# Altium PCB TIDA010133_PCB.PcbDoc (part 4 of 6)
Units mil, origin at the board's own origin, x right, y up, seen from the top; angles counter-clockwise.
Board outline 4100 x 6400 mil, 8 copper layers (Top Layer, Ground 1, Signal 1, Power 1, Ground 2, Signal 2, Power 2, Bottom Layer), stack 60.4 mil thick; 587 components, 322 nets, 1661 pads, 859 vias.
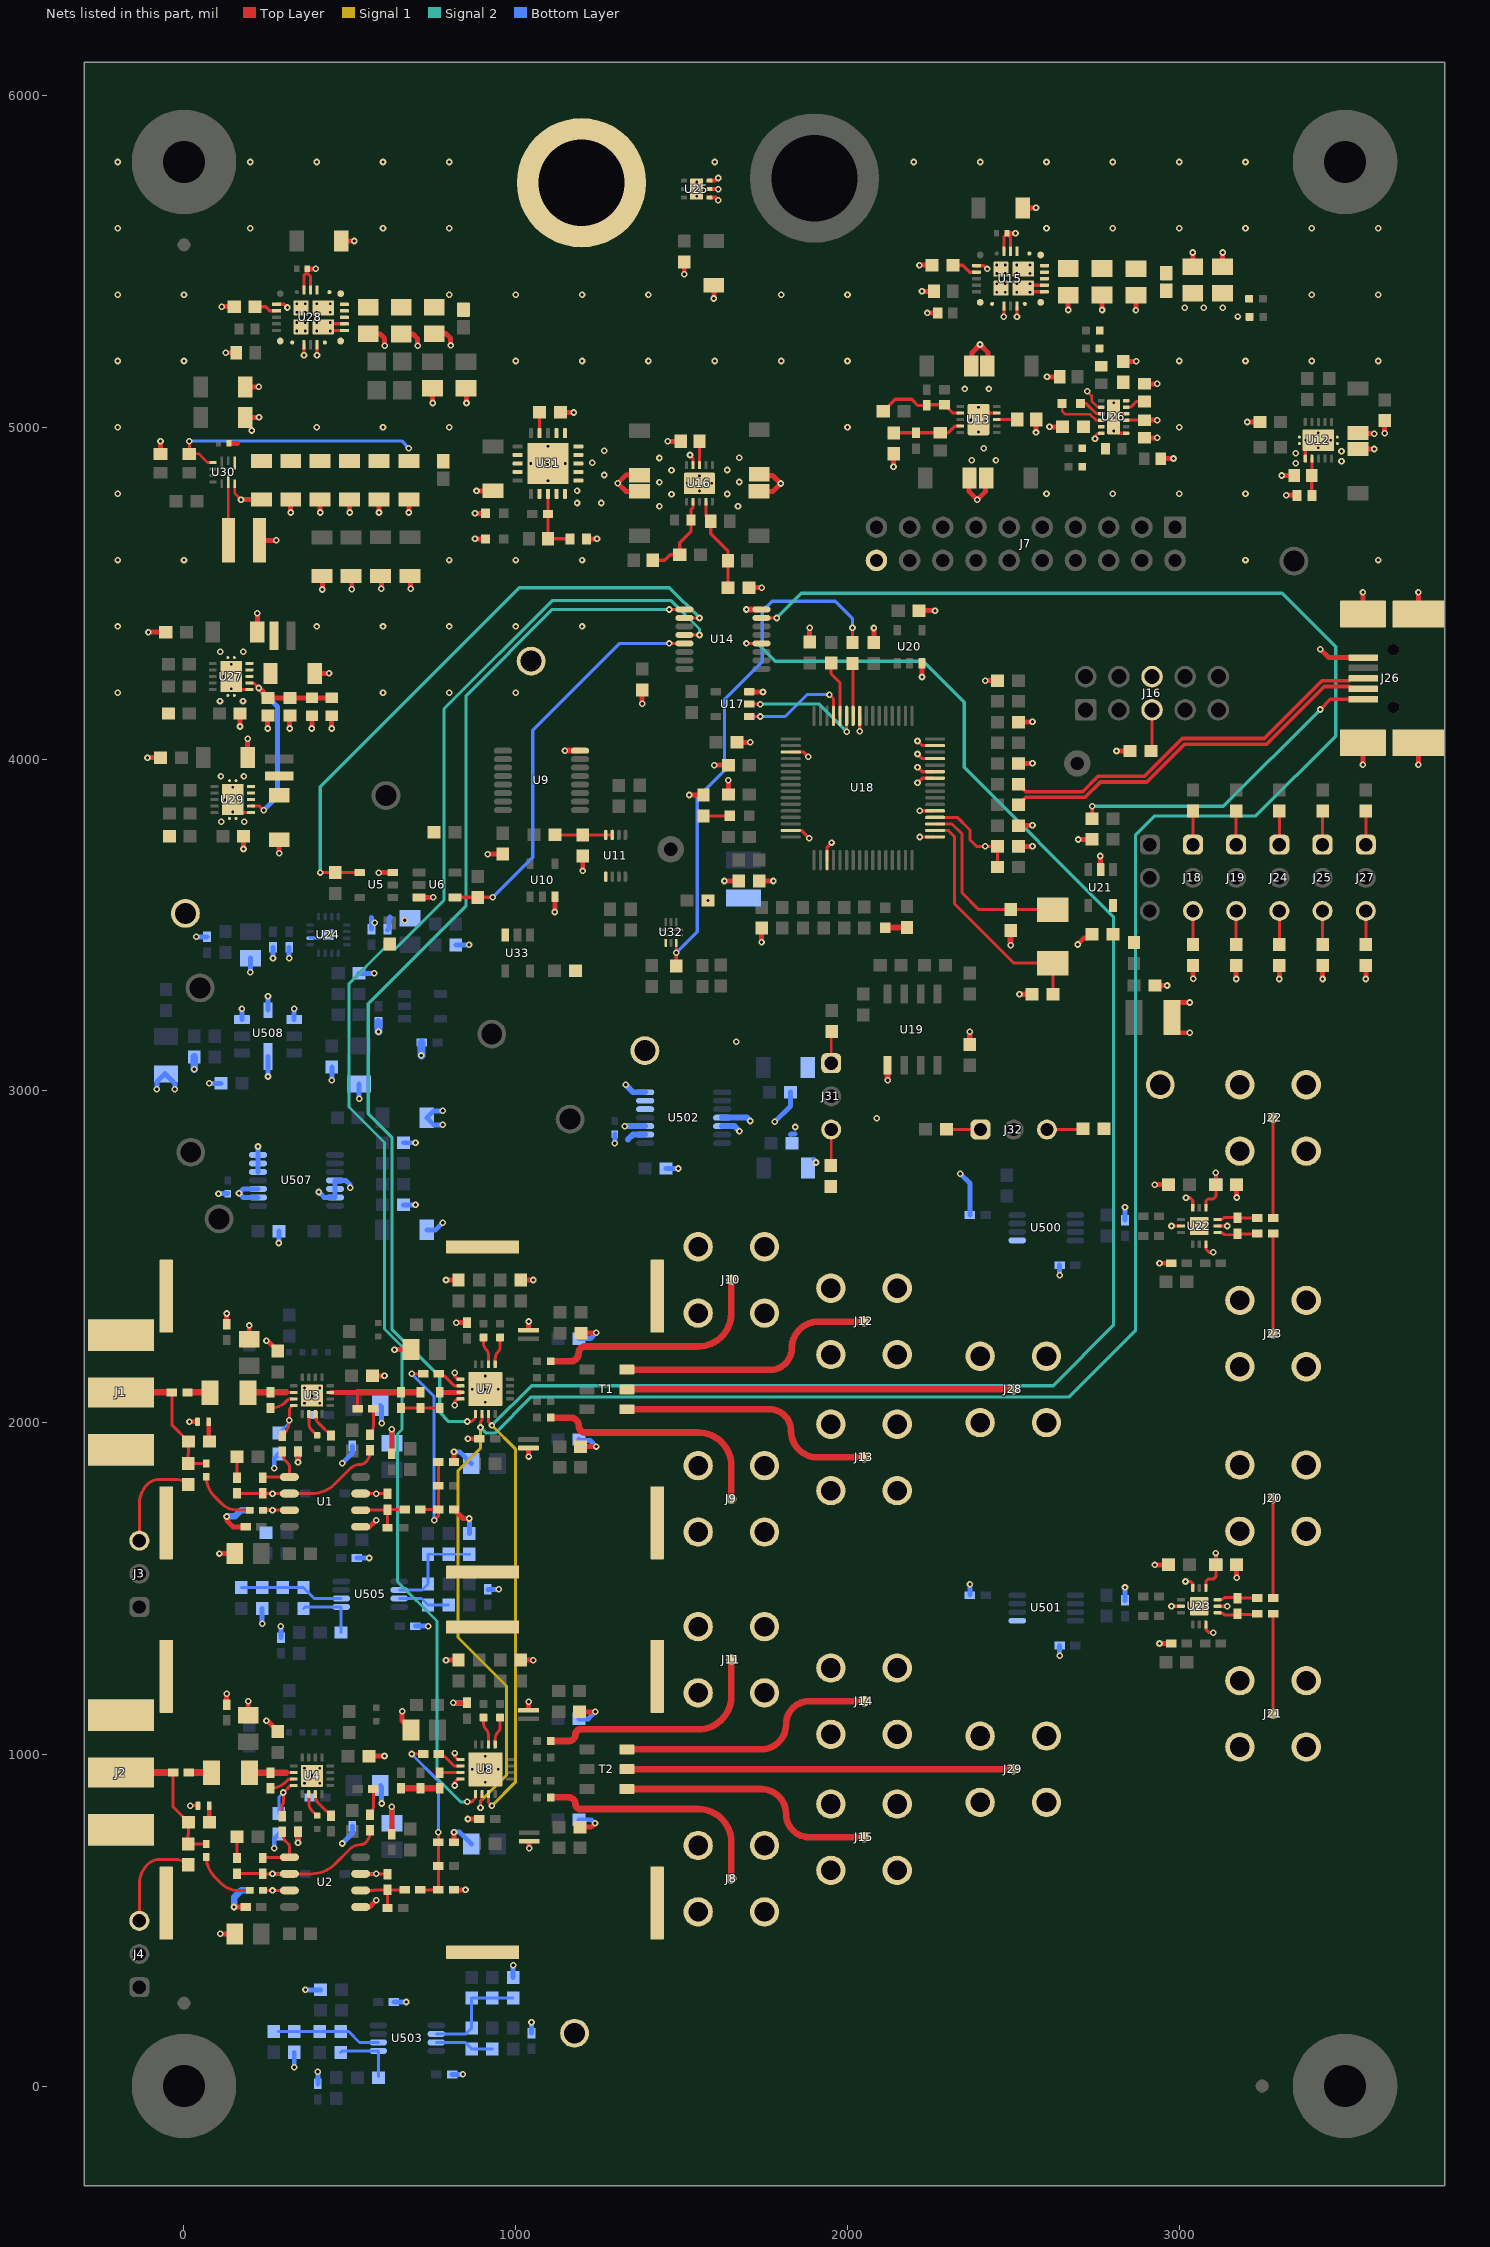
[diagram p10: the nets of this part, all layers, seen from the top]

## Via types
v1: diameter 20, hole 10, Top Layer to Bottom Layer, tented top, 776 vias
v2: diameter 19.68, hole 7.87, Top Layer to Bottom Layer, tented bottom, 82 vias
v3: diameter 19.68, hole 7.87, Top Layer to Bottom Layer, 1 vias

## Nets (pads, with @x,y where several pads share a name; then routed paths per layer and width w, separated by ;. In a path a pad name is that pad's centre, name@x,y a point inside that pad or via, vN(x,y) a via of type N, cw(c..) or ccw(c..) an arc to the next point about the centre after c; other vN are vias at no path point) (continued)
GND: C1.2 C2.2 C3.1 C4.1 C7.2 C8.2 C9.1 C10.1 C13.1 C14.2 C15.2 C16.2 C17.2 C19.2 C20.2 C21.2 C22.1 C23.2 C24.2 C26.2 C27.1 C28.1 C29.2 C30.2 C33.2 C34.2 C35.2 C36.2 C37.2 C39.2 C40.2 C41.2 C42.2 C43.2 C44.2 C45.2 C46.2 C47.2 C48.2 C49.2 C50.2 C51.2 C52.1 C53.1 C54.2 C55.2 C56.2 C57.2 C58.2 C61.2 C64.1 C65.1 C66.1 C68.2 C70.2 C71.2 C76.1 C78.2 C79.2 C80.1 C81.1 C82.1 C83.1 C84.1 C85.1 C86.1 C87.1 C88.1 C89.1 C90.2 C91.2 C92.2 C93.2 C94.2 C95.1 C96.1 C97.1 C98.2 C99.2 C104.1 C105.2 C106.2 C107.2 C108.2 C109.2 C110.2 C111.2 C112.2 C113.1 C114.1 C115.2 C116.2 C117.1 C118.1 C119.1 C121.2 C122.1 C123.2 C124.2 C125.1 C126.1 C127.1 C128.1 C130.2 C131.1 C132.1 C133.1 C134.2 C135.1 C136.2 C137.2 C138.2 C139.2 C140.2 C141.2 C142.2 C143.2 C144.2 C145.2 C146.2 C147.2 C500.2 C501.2 C502.2 C503.2 C504.2 C505.2 C506.2 C507.2 C510.1 C511.1 C512.2 C513.2 C514.2 C523.2 C524.2 C525.2 C526.2 C528.2 C529.2 C530.2 C531.2 C532.2 C534.1 C535.1 C536.2 C537.2 C538.2 C539.2 C540.1 C541.1 C542.2 C543.2 C544.2 C545.2 C546.2 C547.2 C548.2 C549.2 C550.2 C551.1 C552.1 C554.2 C555.2 C556.2 C557.2 C559.2 C560.2 C561.2 C562.2 C563.2 C564.2 C565.2 C566.2 C567.2 C568.2 C569.2 H3.1 H4.1 H5.1 H6.1 H7.1 H8.1 H9.1 H10.1 H11.1 H12.1 H13.1 H14.1 J1.2 J1.3 J1.4 J1.5 J2.2 J2.3 J2.4 J2.5 J7.20 J8.2 J8.3 J8.4 J8.5 J9.2 J9.3 J9.4 J9.5 J10.2 J10.3 J10.4 J10.5 J11.2 J11.3 J11.4 J11.5 J12.2 J12.3 J12.4 J12.5 J13.2 J13.3 J13.4 J13.5 J14.2 J14.3 J14.4 J14.5 J15.2 J15.3 J15.4 J15.5 J16.6 J20.2 J20.3 J20.4 J20.5 J21.2 J21.3 J21.4 J21.5 J22.2 J22.3 J22.4 J22.5 J23.2 J23.3 J23.4 J23.5 J26.5 J26.6 J26.7 J26.8 J26.9 J28.2 J28.3 J28.4 J28.5 J29.2 J29.3 J29.4 J29.5 J30.1 L1.1 L2.1 L16.2 R42.1 R44.1 R48.1 R49.1 R60.1 R61.1 R63.1 R64.1 R70.1 R76.1 R77.1 R82.1 R85.1 R91.1 R98.2 R105.1 R106.1 R110.1 R112.1 R116.1 R117.1 R139.2 R142.1 R149.1 R150.1 R151.1 R157.1 R161.1 R163.1 R166.1 R171.1 R172.1 R175.1 R176.1 R179.1 R503.1 R505.1 R508.2 R511.1 R513.1 R514.1 R515.1 R516.1 R517.1 R522.1 R542.1 R548.2 R550.1 R551.1 R552.1 R553.1 R555.1 TP1.1 TP8.1 TP9.1 TP11.1 TP13.1 U1.5 U2.5 U3.17 U4.17 U5.3 U6.3 U7.5 U7.8 U7.17 U8.5 U8.8 U8.17 U9.8 U10.3 U11.1 U12.6 U12.11 U13.4 U13.11 U14.8 U15.1 U15.2 U15.3 U15.5 U15.6 U15.7 U15.8 U15.9 U15.16 U15.17 U15.20 U15.25 U15.26 U15.28 U16.4 U16.11 U17.3 U18.1 U18.5 U18.10 U18.11 U18.13 U18.15 U18.25 U18.35 U18.47 U18.51 U19.5 U20.3 U21.2 U22.3 U22.5 U22.9 U22.11 U22.13 U23.3 U23.5 U23.9 U23.11 U23.13 U24.6 U24.17 U25.1 U25.2 U25.3 U25.7@1545.46,5718.18 U26.1 U26.4 U26.13 U27.6 U27.11 U28.1 U28.2 U28.3 U28.5 U28.6 U28.7 U28.8 U28.9 U28.16 U28.17 U28.20 U28.25 U28.26 U28.28 U29.6 U29.11 U30.3 U31.2 U31.4 U31.5 U31.6 U31.7 U31.8 U31.9 U31.10 U31.11 U31.12 U31.17 U31.18 U31.19 U31.21 U32.3 U33.3 U500.5 U501.5 U502.2 U502.3 U502.5 U502.6 U502.7 U502.11 U502.12 U507.2 U507.3 U507.5 U507.6 U507.7 U507.11 U507.12 U507.13 U508.3 U508.4 U508.5 U508.8 | length 13695.3
  Top Layer w7.87: U30.3@153.04,4830.24 153.04,4801.23 v1(171.99,4782.28)
  Top Layer w9: v1(19,845) L2.1@42.27,845 ; v1@2211.49,4054.74 2225.36,4040.87 U18.15@2264.25,4040.87
  Top Layer w9.45: U27.11@143.97,4209.63 U27.6@197.12,4209.63 ; v2(147,3840.6) 148.97,3838.63 U29.6@202.12,3838.63 ; v1(1525.46,4916.66) 1534.32,4907.8 U16.4@1534.32,4886.12 ; v2(2417.74,5023.48) 2417.74,5038.05 2422.86,5043.17 U13.4@2450.22,5043.17 ; v2(2802.59,4989.06) 2812.43,4989.06 2819.13,4982.37 U26.1@2839.8,4982.37 ; v2(2802.59,5031.38) 2812.43,5041.22 U26.4@2839.99,5041.22 ; v1(2976.73,1446.17) U23.5@3005.54,1446.17 ; v1(2976.73,2592.43) U22.5@3005.54,2592.43 ; v1(3018.95,1520.77) 3034.4,1520.77 3040.98,1514.2 U23.3@3040.98,1501.29 ; v1(3020.48,2677.9) 3032.29,2677.9 3040.98,2669.21 U22.3@3040.98,2647.55 ; U23.9@3080.35,1391.05 3080.35,1377.04 3090.68,1366.71 v1(3102.68,1366.71) ; U22.9@3080.35,2537.31 3080.35,2523.29 3090.68,2512.96 v1(3102.68,2512.96) ; U23.11@3115.78,1446.17 v1(3144.59,1446.17) ; U22.11@3115.78,2592.43 v1(3144.59,2592.43)
  Top Layer w9.84: U28.20@278.94,5371.12 301.88,5371.12 v1(311.8,5361.2) ; v1(361.61,5217.29) U28.3@361.61,5249.07 ; U28.17@361.61,5414.43 361.61,5457.43 370.71,5466.53 ; C104.1@370.71,5477.25 370.71,5466.53 ; U28.16@381.3,5414.43 381.3,5455.94 370.71,5466.53 ; v1(400.98,5217.29) U28.5@400.98,5249.07 ; v2(440.35,5290.41) 442.32,5292.38 U28.8@483.66,5292.38 ; v2(440.35,5316) 444.29,5312.06 U28.9@483.66,5312.06 ; v1(816.12,905.78) 816.12,915.79 825.48,925.16 U8.8@833.57,925.16 ; v1(816.12,1003.59) 816.12,993.58 825.48,984.21 U8.5@833.57,984.21 ; v1(816.12,2052.03) 816.12,2062.04 825.48,2071.41 U7.8@833.57,2071.41 ; v1(816.12,2149.85) 816.12,2139.84 825.48,2130.47 U7.5@833.57,2130.47 ; U18.47@1829.21,3784.97 1860.93,3784.97 v1(1884.94,3760.96) ; U18.35@1829.21,4021.19 1868.45,4021.19 v1(1882.15,4007.49) ; U18.51@1938.46,3695.4 1938.46,3734.64 v1(1952.16,3748.34) ; v1@2036.89,4082.93 v1(2036.89,4084.18) U18.25@2036.89,4130.44 ; v1(2211.31,3928.75) 2225.01,3942.45 U18.10@2264.25,3942.45 ; v1(2211.31,3975.83) 2225.01,3962.13 U18.11@2264.25,3962.13 ; v1(2211.31,4015.2) 2225.01,4001.5 U18.13@2264.25,4001.5 ; v1@2216.32,3765.28 U18.1@2264.25,3765.28 ; v1@2216.32,3844.02 U18.5@2264.25,3844.02 ; U15.20@2388.98,5487.62 2411.92,5487.62 v1(2421.84,5477.7) ; v1(2471.65,5333.8) U15.3@2471.65,5365.57 ; U15.17@2471.65,5530.93 2471.65,5573.94 C13.1@2480.75,5583.03 ; C13.1@2480.75,5585 C13.1@2480.75,5583.03 ; U15.16@2491.34,5530.93 2491.34,5572.44 C13.1@2480.75,5583.03 ; v1(2511.02,5333.8) U15.5@2511.02,5365.57 ; v2(2550.39,5406.91) 2552.36,5408.88 U15.8@2593.7,5408.88 ; v2(2550.39,5432.5) 2554.33,5428.57 U15.9@2593.7,5428.57 ; U12.6@3380.26,4905.85 3380.26,4959 v2(3382.23,4960.96)
  Top Layer w11.81: U25.1@1583.84,5692.59 1602.91,5692.59 v1(1610.82,5684.67) ; U25.2@1583.84,5718.18 v1(1610.7,5718.18) ; U25.3@1583.84,5743.77 1602.91,5743.77 v1(1610.82,5751.68)
  Top Layer w13.78: v1(16.37,2002.3) L1.1@40.62,2002.29
  Top Layer w15: v1@-109.88,4004.34 R172.1@-70.99,4004.34 ; v1(-107.23,4382.46) R106.1@-55.53,4382.46 ; R175.1@-70.89,4920 v1(-70.89,4958.39) ; v1(106.8,1604.98) C4.1@152.81,1604.98 ; v1(108.81,458.73) C3.1@152.81,458.73 ; v1(113.82,5364) C147.2@151.5,5364 ; v1(125.63,5225) R171.1@157.41,5225 ; C2.2@128.74,1149.83 v1(128.74,1182.57) ; C1.2@128.74,2296.08 v1(128.74,2328.83) ; v1(128.9,1716.99) 128.9,1704.7 147.8,1685.8 C10.1@185.56,1685.8 ; C113.1@135.5,4952 161.37,4952 ; v1(150.81,539.55) C9.1@185.56,539.55 ; v1@168.66,4098.53 R112.1@168.66,4137.42 ; v1(171.99,4782.28) C117.1@233.46,4782.28 ; v1@179.25,3729.11 R176.1@179.25,3768 ; C116.2@186.1,5122.02 v1(225.76,5122.02) ; C115.2@186.52,5030.35 v1(226.17,5030.35) ; C136.2@191.82,4004.42 v1(191.82,4061.75) ; C8.2@193.69,1117.59 v1(193.69,1159.59) ; C7.2@196.69,2250.84 v1(196.69,2292.84) ; C124.2@221.3,4383.56 v1(221.3,4439.44) ; L16.2@227.67,4659.45 v1(278.06,4659.45) ; v1(248.46,1100.66) 251.58,1100.66 C16.2@283.22,1069.01 ; v1(248.46,2246.91) 251.58,2246.91 C15.2@283.22,2215.27 ; v1@252.25,4092.28 C132.1@252.25,4131.17 ; v1@287,3716.28 C134.2@287,3755.17 ; v1@318.44,4092.28 C133.1@318.44,4131.17 ; v1(321.7,4743.23) C118.1@321.7,4782.28 ; v1(343.72,733.66) C20.2@343.72,766.41 ; v1(343.72,1879.92) C19.2@343.72,1912.66 ; C104.1@371.46,5478 v1(397.33,5478) ; v1@385.25,4092.28 R116.1@385.25,4131.17 ; C123.2@398.36,4258.53 v1@437.25,4258.53 ; v1(410.39,4743.23) C125.1@410.39,4782.28 ; v1(417.04,4511.36) C140.2@417.04,4550.97 ; v1@445.25,4092.28 R117.1@445.25,4131.17 ; C109.2@473.82,5562 v1(513.47,5562) ; v1(499.4,4743.23) C126.1@499.4,4782.28 ; v1(505.72,4512) C139.2@505.72,4551.04 ; U2.5@532.36,539.55 559.91,539.55 v1(579.91,559.55) ; U1.5@532.36,1685.81 559.91,1685.81 v1(579.91,1705.81) ; C110.2@555.41,5281.85 590.8,5281.85 604.77,5267.88 v1(604.77,5246.47) ; C23.2@557.85,994.64 v1(604.54,994.64) ; C24.2@567.85,2140.9 v1(604.54,2140.9) ; v1@587.72,3657.93 U5.3@629.7,3657.93 ; v1(587.85,4743.23) C127.1@587.85,4782.28 ; v1@594.76,4513.76 C138.2@594.76,4553.17 ; C27.1@626.44,1905.32 v1(626.44,1980.08) ; C28.1@626.6,759.22 v1@626.6,841.85 ; v1(634.68,2219.82) C29.2@684.23,2219.82 ; C111.2@654.83,5281.57 690.21,5281.57 704.18,5267.6 v1(704.18,5246.19) ; v1(657.51,1129.58) 657.51,1100.29 C30.2@684.23,1073.57 ; v1(677.7,4743.23) C128.1@677.7,4782.28 ; v1(683.44,4513.76) C137.2@683.44,4553.81 ; U6.3@708.84,3583.13 v1@750.82,3583.13 ; v1(749.55,5073.34) C145.2@749.55,5118.31 ; C112.2@754.37,5282.42 789.76,5282.42 803.72,5268.45 v1(803.72,5247.04) ; v1(789.89,1283.56) R49.1@827.59,1283.56 ; v1(789.89,2429.81) R48.1@827.59,2429.81 ; v1(812.12,1154.88) C37.2@853.42,1154.88 ; C34.2@813.97,591.49 v1(848.72,591.49) ; R44.1@813.97,734.61 v1(813.97,765.33) ; C33.2@813.97,1737.75 840.99,1710.72 v1(860.28,1710.72) ; R42.1@813.97,1880.86 v1(813.97,1911.59) ; v1(820.48,2301.02) C36.2@853.53,2301.02 ; v1(851.59,5073.38) C146.2@851.59,5118.35 ; v1(855.91,804.88) C40.2@890.66,804.88 ; v1(855.91,1951.14) C39.2@890.66,1951.14 ; v1(877.1,4664) C131.1@908.88,4664 ; v1(877.1,4741) C135.1@908.88,4741 ; v1(881.9,4808.44) C130.2@932,4808.44 ; v1(915.99,3713.45) C41.2@961.5,3713.45 ; R61.1@1015.31,1283.56 v1(1053.01,1283.56) ; R60.1@1015.31,2429.81 v1(1053.01,2429.81) ; C46.2@1038.87,1135.55 v1(1038.87,1158.24) ; v1(1038.87,1897.39) C45.2@1038.87,1920.08 ; C44.2@1038.87,2281.8 v1(1038.87,2304.49) ; v1(1040.74,716.47) C47.2@1040.74,737.33 ; v1(1118.13,3539.26) U10.3@1118.13,3584.77 ; C141.2@1134.72,5045 v1(1174.72,5045) ; C50.2@1192.96,1128.13 v1(1240.08,1128.13) ; C51.2@1193.63,780.31 1227.67,780.32 v1(1239.23,791.87) ; C49.2@1195.79,1927.55 v1(1242.73,1927.55) ; C48.2@1196.53,2270.11 v1@1242.34,2270.11 ; v1(1202.08,3662.95) C52.1@1202.08,3708.45 ; R179.1@1213.21,4664 v1(1244.99,4664) ; C78.2@1373,4856.07 1332.07,4856.07 v1(1307.76,4831.76) 1332.23,4807.3 C79.2@1373.14,4807.3 ; v1@1381.09,4166.97 C55.2@1381.09,4208.95 ; v1(1458.2,4958) C80.1@1496.91,4958 ; v1(1508,5461.32) C57.2@1508,5499.01 ; v1(1523.43,3891.93) R110.1@1566.06,3891.93 ; v1(1597,5388.49) C61.2@1597,5428.14 ; v1(1598.39,3981.82) C65.1@1641.02,3981.82 ; v1(1629.14,3632.41) C70.2@1671.77,3632.41 ; C66.1@1641.02,3893.39 v1(1641.02,3936.02) ; C64.1@1666.61,4050.71 v1(1707.23,4050.71) ; R105.1@1702.99,4517 v1(1741.71,4517) ; U17.3@1704.02,4203.14 1704.46,4202.7 1745.09,4202.7 v1(1745.53,4202.26) ; C71.2@1733.14,4806.2 1774.04,4806.2 v1(1798.51,4830.67) 1774.2,4854.98 C68.2@1733.27,4854.98 ; C76.1@1734.18,3632.41 v1(1776.81,3632.41) ; v1(1741.14,3447.68) C81.1@1741.14,3490.31 ; C82.1@1886.08,4352.56 v1(1886.08,4396.36) ; C83.1@2079.77,4351.38 v1(2079.77,4395.18) ; v1(2139,4881.76) R85.1@2139,4920.47 ; C84.1@2216.16,4447.41 v1(2263.8,4447.41) ; v1(2216.96,5489) C144.2@2254.65,5489 ; v1(2224.83,5410) R82.1@2260.55,5410 ; v1(2224.88,4247.61) U20.3@2224.88,4288.39 ; C26.2@2367.06,4847 2367.06,4806.07 v1(2391.36,4781.76) 2415.83,4806.23 C35.2@2415.83,4847 ; C43.2@2375.44,5184.48 2375.44,5225.41 v1(2399.74,5249.72) 2424.21,5225.25 C42.2@2424.21,5185 ; v1(2415.75,4236.45) C89.1@2452.43,4236.45 ; C13.1@2480.75,5585 v1(2506.62,5585) ; R139.2@2515.43,3799.63 v1@2557.41,3799.63 ; C86.1@2515.43,3737.23 v1@2557.41,3737.23 ; C87.1@2515.43,3986.84 v1@2557.41,3986.84 ; C88.1@2515.43,4111.64 v1@2557.41,4111.64 ; C105.2@2528.76,5661.92 v1(2568.41,5661.92) ; v1(2568.54,4984.77) C53.1@2568.54,5023.48 ; v1(2601.62,5152.29) R98.2@2640.33,5152.29 ; v1(2609.29,5001.85) C121.2@2648.01,5001.85 ; v1(2665.55,5353.93) C106.2@2665.55,5398.9 ; v1(2694.43,3441.24) 2714.35,3461.17 2726.67,3461.17 C93.2@2737.88,3472.37 ; v1@2695.89,3757.97 C92.2@2737.88,3757.97 ; U21.2@2762.9,3665.52 v1@2762.9,3707.5 ; v1(2767.59,5353.98) C107.2@2767.59,5398.95 ; v1(2811.18,4024.35) R142.1@2852.02,4024.35 ; C122.1@2832,5198.99 v1(2870.72,5198.99) ; v1(2869.65,5352.79) C108.2@2869.65,5397.75 ; C119.1@2895,4968.39 v1(2933.72,4968.39) ; C114.1@2895,5131.15 v1(2933.72,5131.15) ; v1(2925.99,1570.84) C97.1@2967.67,1570.84 ; v1(2925.99,2717.1) C96.1@2967.67,2717.1 ; C95.1@2926.85,3317.56 v1(2963.54,3317.56) ; v1(2940.78,1333.94) R150.1@2975.52,1333.94 ; v1(2940.78,2480.19) R149.1@2975.52,2480.19 ; R91.1@2944.21,4906 v1(2982.93,4906) ; v1(3031.67,3175.09) 3001.29,3175.09 2978.03,3198.35 C94.2@2978.03,3220.71 2978.03,3243.07 3001.29,3266.33 v1(3031.67,3266.33) ; C142.2@3041,5483.98 v1(3041,5526.98) ; v1@3041.57,3338.52 R151.1@3041.57,3378.36 ; C143.2@3131,5483.98 v1(3131,5526.98) ; v1(3171.8,3337.13) R157.1@3171.8,3378.36 ; v1(3173.34,1532.14) C99.2@3173.34,1570.84 ; v1(3173.34,2678.4) C98.2@3173.34,2717.1 ; v1(3205.32,5016.08) R76.1@3243.01,5016.08 ; v1(3302.04,3337.13) R161.1@3302.04,3378.36 ; v1(3309.11,4855) C22.1@3346.8,4855 ; v1(3322.72,4795.64) R77.1@3354.03,4795.64 ; v1(3425.74,4331.25) 3450.81,4306.18 J26.5@3554.92,4306.18 ; v1(3432.28,3337.13) R163.1@3432.28,3378.36 ; C14.2@3538.61,4935.02 v1(3588.11,4935.02) ; C21.2@3538.61,4981.18 v1(3588.11,4981.18) ; v1(3553.94,3982.93) J26.7@3553.94,4049.29 ; J26.9@3553.94,4437.09 v1(3553.94,4503.45) ; v1(3562.51,3337.13) R166.1@3562.51,3378.36 ; v1(3619.26,4982.41) R70.1@3619.26,5020.09 ; v1(3721.26,3982.93) J26.6@3721.26,4049.29 ; J26.8@3721.26,4437.09 v1(3721.26,4503.45)
  Top Layer w17.72: v1(1148.34,4025.4) U9.8@1193.85,4025.4 ; v1(1695.46,4451.08) U14.8@1740.97,4451.08 ; v1(2121.09,3032.24) U19.5@2121.09,3077.04 ; C85.1@2368.57,3140.03 v1(2368.57,3177.78) ; v1(2492.03,3438.65) C90.2@2492.03,3482.86 ; v1(2518.67,3291.29) C91.2@2556.42,3291.29
  Bottom Layer w6: 412.32,3460.15 413.49,3461.33 426.85,3461.33 v3(435.51,3470)
  Bottom Layer w9: U24.6@380.39,3460.15 412.32,3460.15
  Bottom Layer w15: v1(-81.81,3004.78) -81.81,3027.35 -57.19,3051.96 -27.48,3022.25 v1(-27.48,3004.78) ; v1(36.71,3464.09) C567.2@69.46,3464.09 ; v1(75.91,3022.59) R553.1@111.61,3022.59 ; v1(103.83,2689.86) R555.1@131.92,2689.86 ; U508.3@174.6,3214.49 v1(174.6,3247.27) ; v1(200.18,3357.84) C566.2@200.18,3399.84 ; U507.2@223.11,2678.73 178.35,2678.73 v1(165.74,2691.35) 178.71,2704.32 U507.3@223.11,2704.32 ; U507.5@223.11,2755.5 U507.6@223.11,2781.09 U507.7@223.11,2806.68 ; U507.7@223.11,2807.95 v1(223.11,2832.28) ; v1(235.75,1393.25) R550.1@235.75,1439.13 ; v1(253.34,3043.13) U508.8@253.34,3103.46 ; U508.4@253.34,3243.23 v1(253.34,3285.23) ; v1(268.49,3399.85) C565.2@268.49,3432.59 ; v1(272.05,716.37) 272.05,745.12 C563.2@286.05,759.12 ; v1(272.05,1862.63) 272.05,1891.37 C562.2@286.05,1905.37 ; v1(286.1,2541.12) R548.2@286.1,2576.82 ; C564.2@291.96,1351.5 v1(291.96,1385.96) ; v1(317.11,3399.85) C561.2@317.11,3432.59 ; U508.5@332.08,3214.49 v1(332.08,3247.27) ; v1(332.33,56.28) R542.1@332.33,101.63 ; v1(343.72,733.66) C560.2@343.72,766.41 ; v1(343.72,1879.92) C559.2@343.72,1912.66 ; v1(366.03,290.04) R505.1@412.08,290.04 ; C557.2@403.4,6.5 v1(403.4,42.88) ; v1(406.46,2694.96) 422.7,2678.73 U507.13@455.4,2678.73 U507.12@455.4,2704.32 U507.11@455.4,2729.91 488.09,2729.91 500.95,2717.06 v1(500.95,2707.55) ; v1(445.55,3032.22) C554.2@445.55,3071.5 ; v1(477.34,731.08) 507.45,761.19 C552.1@507.45,783.25 ; v1(477.34,1877.34) 507.45,1907.45 C551.1@507.45,1929.51 ; C550.2@521.05,1591.52 v1(558.2,1591.52) ; v1(528.03,2975.91) C548.2@528.03,3020.31 ; C549.2@528.03,3354.36 v1(573.78,3354.36) ; C547.2@564.76,3487.4 564.76,3521.81 ; C544.2@592,905.47 596,901.47 v1(596,851.47) ; C545.2@592,2051.73 596,2047.73 v1(596,1997.73) ; C543.2@613.38,3485.43 617.69,3489.74 617.69,3518.36 621.34,3522.01 621.34,3523.36 ; C540.1@626.44,1938.08 v1(626.44,1980.08) ; C541.1@626.75,792.14 v1(626.75,842.01) ; C542.2@632.87,253.22 v1(669.72,253.22) ; C539.2@661.04,2656.29 v1(697.72,2656.29) ; C538.2@661.24,2843.49 v1(697.93,2843.49) ; C537.2@697.62,1386 v1(736.53,1386) ; C535.1@731.9,2581.09 758.73,2581.09 v1(779.83,2602.19) ; v1(780.03,2897.59) 753.2,2897.59 C534.1@732.11,2918.69 753.2,2939.79 v1(780.03,2939.79) ; C531.2@808.07,35.15 v1(840.82,35.15) ; v1(812.12,1154.88) C528.2@853.42,1154.88 ; v1(813.97,765.33) 830.96,765.33 C524.2@866.41,729.88 ; v1(813.97,1911.59) 830.96,1911.59 C525.2@866.41,1876.14 ; C530.2@819.29,3440.15 v1(859.4,3440.15) ; v1(820.48,2301.02) C529.2@853.53,2301.02 ; R522.1@860.28,1666 v1(860.28,1710.72) ; C526.2@915.79,1497.41 v1(948.55,1497.41) ; R517.1@992.1,327.69 v1(992.1,364.38) ; C523.2@1047.55,159.11 v1(1047.55,191.85) ; R514.1@1191.04,802.61 1228.13,802.61 1238.88,791.87 v1(1239.23,791.87) ; R513.1@1191.04,1106.76 1218.7,1106.76 v1(1240.08,1128.13) ; R516.1@1191.04,1948.87 1194.08,1945.84 1224.44,1945.84 v1(1242.73,1927.55) ; R515.1@1191.04,2253.01 1225.23,2253.01 v1(1242.66,2270.44) ; v1(1298.91,2842.41) R511.1@1298.91,2869.32 ; R508.2@1453.1,2765.99 v1(1489.78,2765.99) ; v1(1781.19,2906.79) 1828.23,2953.83 C512.2@1828.23,2995.84 ; 1828.03,2867.89 1829.68,2869.54 1841.91,2869.54 ; C511.1@1898.9,2792.69 1905.33,2786.26 v1(1905.33,2784.02) ; v1(2340.09,2750.23) 2369.21,2721.12 C506.2@2369.21,2625.7 ; C507.2@2369.2,1479.45 v1(2369.21,1512.2) ; v1(2639.89,1297.34) C503.2@2639.89,1328.15 ; v1(2639.89,2443.59) C502.2@2639.89,2474.41 ; C501.2@2836.56,1463.7 v1(2836.56,1502.98) ; C500.2@2836.56,2609.96 v1(2836.56,2649.23)
  Bottom Layer w17.72: v1(1328.69,2893.48) U502.3@1390.1,2893.48 ; v1(1331.55,3017.88) 1353.58,2995.84 U502.7@1390.1,2995.84 ; 1338.14,2852.99 1353.03,2867.89 U502.2@1390.1,2867.89 ; U502.12@1622.39,2893.48 1659.46,2893.48 v1(1674.36,2878.58) ; U502.11@1622.39,2919.07 1697.01,2919.07 v1(1707.04,2909.04)
  Bottom Layer w19.68: v1(128.9,1716.99) 153.17,1716.99 171.99,1735.81 R551.1@198.34,1735.81 ; v1(150.81,539.55) 150.81,568.38 171.99,589.55 R552.1@198.34,589.55
  Bottom Layer w23.62: v1(30.75,3064.81) C568.2@30.75,3101.5 ; v1(586.51,3178.51) C546.2@586.51,3207.32 ; v1(715.59,3106.74) C532.2@715.59,3146.18
  other v1: 1842.32,2890.97 2088.06,2917.02 1665.07,3148.04 3042.25,3337.84 575.27,3506.27 665.49,3514.11 1579.36,3573.76 751.33,3583.64 587.21,3657.43 2762.39,3708.01 287.13,3716.15 179.38,3728.98 2557.91,3737.74 2695.39,3757.46 2217.82,3765.11 2557.91,3800.14 112.01,3811.25 181.36,3811.25 2217.82,3843.85 111.28,3948.73 180.63,3948.73 2557.91,3987.35 -110.01,4004.21 2211.31,4054.57 252.39,4092.15 318.57,4092.15 385.39,4092.15 445.39,4092.15 168.79,4098.4 2557.91,4112.15 1381.59,4166.47 108.54,4174.94 177.89,4174.94 -200,4200 600,4200 800,4200 1000,4200 437.38,4258.66 108.86,4323.76 178.22,4323.76 -200,4400 400,4400 600,4400 800,4400 1000,4400 1200,4400 594.76,4513.12 -200,4600 0,4600 800,4600 1000,4600 1200,4600 3200,4600 3600,4600 1433.16,4762.22 1670.21,4762.67 1184.98,4772.2 1257.63,4772.2 1469.49,4798.54 1637.88,4798.99 -200,4800 2600,4800 2800,4800 3000,4800 3200,4800 1184.98,4808.52 1433.16,4834.87 1674.21,4835.32 1267.25,4856.64 1469.49,4871.19 1637.88,4871.64 3351.22,4892.12 1230.92,4892.97 3489.27,4898.09 2374.95,4900.96 2447.61,4900.96 1433.16,4907.52 1674.21,4907.97 3351.22,4921.94 3489.27,4927.91 1267.25,4929.29 2411.28,4937.29 204.25,4990.39 -200,5000 400,5000 600,5000 800,5000 2000,5000 3000,5000 2353.86,5115.91 2426.51,5115.91 -200,5200 0,5200 1000,5200 1200,5200 1400,5200 1600,5200 1800,5200 2000,5200 3000,5200 3200,5200 3400,5200 3600,5200 -200,5400 0,5400 800,5400 1000,5400 1200,5400 1400,5400 1800,5400 2000,5400 3400,5400 3600,5400 -200,5600 200,5600 600,5600 800,5600 2600,5600 2800,5600 3000,5600 3200,5600 3400,5600 3600,5600 -200,5800 200,5800 400,5800 600,5800 800,5800 1600,5800 2200,5800 2400,5800 2600,5800 2800,5800 3000,5800 3200,5800
  other v2: 363.17,912.16 408.84,912.16 908.38,915.31 386,935 869.01,954.68 908.38,954.68 947.75,954.68 363.17,957.83 408.84,957.83 908.38,994.05 363.17,2058.42 408.84,2058.42 908.38,2061.57 386,2081.25 869.01,2100.94 908.38,2100.94 947.75,2100.94 363.17,2104.09 408.84,2104.09 908.38,2140.31 124.36,3878 169.64,3878 147,3915.4 142,4211.6 119.36,4249 164.64,4249 142,4286.4 1554,4808.36 1516.6,4831 1591.4,4831 1097.32,4838.95 1554,4853.64 1045.15,4891.12 1097.32,4891.12 1149.48,4891.12 3419.63,4938.33 1097.32,4943.28 3457.03,4960.96 3419.63,4983.6 2395.1,4986.08 2372.47,5023.48 2395.1,5060.89 2802.59,5073.71 339.96,5290.41 365.55,5290.41 400,5290.41 339.96,5316 365.55,5316 400,5316 339.96,5347.5 365.55,5347.5 339.96,5373.09 365.55,5373.09 2450,5406.91 2475.59,5406.91 2510.04,5406.91 2450,5432.5 2475.59,5432.5 2510.04,5432.5 2450,5464 2475.59,5464 2450,5489.59 2475.59,5489.59 1545.46,5696.52 1545.46,5739.83
I2C_CLK: R130.1 U18.26 | length 159.2
  Top Layer w9: R130.1@2015.2,4288.78 2017.2,4286.78 U18.26@2017.2,4130.44
I2C_OE: U17.1 U18.29 | length 338
  Top Layer w9: U17.1@1704.02,4128.34 v1(1736.76,4128.34) ; v1(1945.69,4194.29) 1958.15,4181.83 U18.29@1958.15,4130.44
  Bottom Layer w9: v1(1736.76,4128.34) 1812.42,4128.34 1878.37,4194.29 v1(1945.69,4194.29)
I2C_RDATA: R128.1 U18.28 | length 170
  Top Layer w9: R128.1@1950.64,4289.17 1950.64,4257.64 1977.83,4230.45 U18.28@1977.83,4130.44
I2C_WDATA: U17.2 U18.27 | length 376
  Top Layer w9: U17.2@1704.02,4165.74 v1(1736.76,4165.74) ; v1@1997.52,4082.93 U18.27@1997.52,4130.44
  Signal 2 w9: v1(1736.76,4165.74) 1915.23,4165.74 v1(1998.13,4082.84)
LM27762_IN: C119.2 C142.1 C143.1 FB1.2 R78.1 R79.1 R80.2 U26.3 U26.8 U26.12 | length 227.4
  Top Layer w8: v1(2722.65,5108.91) 2736.39,5095.17 2736.39,5078.99 2754.47,5060.91 U26.8@2765.19,5060.91
  Top Layer w9: v1(2746.43,4965.63) 2746.43,4974.09 2754.08,4981.75 U26.12@2764.77,4981.75 ; U26.3@2839.99,5021.54 C119.2@2895,5021.54
  Top Layer w15: v1(2240.58,5345) R80.2@2272.36,5345 ; C119.2@2895,5021.54 v1(2933.72,5021.54)
  other v1: 3176.21,5333.98 3016.37,5360.65 3073.63,5360.65 3130.89,5360.65
LMH6518_SCK: U7.11 U8.11 U14.4 | length 6121.4
  Top Layer w9: U8.11@918.22,879.88 918.22,855.08 v1(928.22,845.08) ; U7.11@918.22,2026.14 918.22,2001.33 v1(928.22,1991.33)
  Top Layer w10: v1(1695.46,4348.72) U14.4@1740.97,4348.72
  Signal 1 w9: v1(928.22,845.08) 998.81,915.67 998.81,1920.75 v1(928.22,1991.33)
  Signal 2 w10: v1(928.22,1991.33) 1048.17,2111.28 2620.25,2111.28 2801.82,2292.85 2801.82,3525.18 2351.65,3975.35 2351.65,4171.57 2228.21,4295 1782.07,4295 1728.36,4348.72 v1(1695.46,4348.72)
LMH6518_SCS0: U7.9 U14.9 | length 3273.9
  Top Layer w9: v1(853.44,2003.01) 867.11,2003.01 878.85,2014.75 U7.9@878.85,2026.14
  Top Layer w10: v1(1463.18,4451.08) U14.9@1508.69,4451.08
  Signal 2 w10: v1(853.44,2003.01) 798.11,2003.01 770.52,2030.6 770.52,2137.72 626.81,2281.43 626.81,2859.52 555.18,2931.16 555.18,3263.14 850.25,3558.2 850.25,4190.9 1110.43,4451.08 v1(1463.18,4451.08)
LMH6518_SCS1: U8.9 U14.12 | length 4649.6
  Top Layer w9: v1(853.44,856.75) 867.11,856.75 878.85,868.5 U8.9@878.85,879.88
  Top Layer w10: U14.12@1508.69,4374.31 v1(1554.19,4374.31)
  Signal 2 w9: v1(853.44,856.75) 833.32,856.75 762.69,927.38 762.69,1401.66 643.92,1520.43 643.92,1965.74 657.18,1978.99 657.18,2229.14 604.26,2282.07 604.26,2844.01 497.35,2950.91 497.35,3323.11 601.52,3427.28 636.44,3427.28 784.02,3574.86 784.02,4151.5 1109.95,4477.42 1468.66,4477.42 1554.19,4391.89 v1(1554.19,4374.31)
LMH6518_SDIO: U7.10 U8.10 U14.7 | length 7781.4
  Top Layer w9: v1(893.87,839.05) 893.87,855.98 898.53,860.65 U8.10@898.53,879.88 ; v1(893.87,1985.3) 893.87,2002.24 898.53,2006.9 U7.10@898.53,2026.14
  Top Layer w10: U14.7@1740.97,4425.49 v1(1786.47,4425.49)
  Signal 1 w9: v1(893.87,839.05) 893.87,858.31 972.11,936.55 972.11,1206.02 826.22,1351.91 826.22,1855.08 893.87,1922.73 v1(893.87,1985.3)
  Signal 2 w10: v1(893.87,1985.3) 910.84,1968.33 937.75,1968.33 1046.46,2077.05 2669.24,2077.05 2868.21,2276.03 2868.21,3770.53 2926.31,3828.63 3230.93,3828.63 3471.78,4069.48 3471.78,4339.07 3310.72,4500.14 1861.12,4500.14 v1(1786.47,4425.49)
LMH6518_u2a_SCS0: R23.1 U5.4 U14.10 | length 1854.6
  Top Layer w10: v1(410.42,3657.93) U5.4@531.15,3657.93 ; U14.10@1508.69,4425.49 v1(1554.19,4425.49)
  Signal 2 w10: v1(410.42,3657.93) 410.42,3916.22 1010.65,4516.45 1463.23,4516.45 v1(1554.19,4425.49)
LMH6518_u2a_SCS1: R50.1 U6.4 U14.13 | length 1232.8
  Top Layer w10: U6.4@817.11,3583.13 R50.1@885.22,3583.13 v1(930.73,3583.13) ; v1(1463.18,4348.72) U14.13@1508.69,4348.72
  Bottom Layer w10: v1(930.73,3583.13) 1051.46,3703.86 1051.46,4086.47 1313.7,4348.72 v1(1463.18,4348.72)
NetC5_1: C5.1 R15.1 U3.2 | length 146.7
  Top Layer w9.45: 307.9,2091.1 U3.2@330.88,2091.1
  Top Layer w20: C5.1@184.22,2091.1 R15.1@261.14,2091.1 307.9,2091.1
NetC5_2: C5.2 R5.2 | length 68.3
  Top Layer w20: R5.2@10.62,2091 C5.2@78.91,2091
NetC6_1: C6.1 R16.1 U4.2 | length 131.9
  Top Layer w9.45: 307.9,944.84 U4.2@330.88,944.84
  Top Layer w20: C6.1@199,945 R16.1@261.14,944.84 307.9,944.84
NetC6_2: C6.2 R6.2 | length 69.2
  Top Layer w20: R6.2@14.62,945 83.16,945 C6.2@83.62,944.54
NetC11_1: C11.1 R17.1 U1.1 | length 164.5
  Top Layer w9: C11.1@237.3,1833.55 cw(c242.76,1828.09) 242.76,1835.81 U1.1@317.8,1835.81 317.8,1867.01 ccw(c303.37,1867.01) 313.57,1877.21 308.71,1882.07 cw(c339.36,1912.72) R17.1@296.02,1912.72
NetC11_2: C11.2 R11.2 R30.1 R540.1 U1.2 | length 511.3
  Top Layer w9: R11.2@159.5,1786.3 C11.2@237.3,1786.3 237.8,1785.8 v1(266.69,1785.8) U1.2@317.8,1785.81 384.01,1785.81 ccw(c384.01,1885.81) 454.72,1815.1 500.26,1860.64 cw(c531.55,1829.36) 531.55,1873.6 ccw(c531.55,1896.35) 547.64,1880.26 ccw(c516,1911.9) 560.74,1911.9 R30.1@560.74,1916.6
  Bottom Layer w9: v1(266.69,1785.8) R540.1@317.81,1785.8
NetC12_1: C12.1 R18.1 U2.1 | length 164.5
  Top Layer w9: C12.1@237.3,687.29 cw(c242.76,681.83) 242.76,689.55 U2.1@317.8,689.55 317.8,720.76 ccw(c303.37,720.76) 313.57,730.96 308.71,735.82 cw(c339.36,766.46) R18.1@296.02,766.46
NetC12_2: C12.2 R12.2 R31.1 R539.1 U2.2 | length 511.3
  Top Layer w9: R12.2@159.5,640.05 C12.2@237.3,640.05 237.8,639.55 v1(266.69,639.55) 317.81,639.55 384.01,639.55 ccw(c384.01,739.55) 454.72,668.84 500.26,714.39 cw(c531.55,683.1) 531.55,727.35 ccw(c531.55,750.09) 547.64,734.01 ccw(c516,765.65) 560.74,765.65 R31.1@560.74,770.35
  Bottom Layer w9: v1(266.69,639.55) R539.1@317.81,639.55
NetC22_2: C22.2 R77.2 U12.7 | length 110.8
  Top Layer w9.29: C22.2@3399.95,4855 U12.7@3399.95,4905.85
  Top Layer w10: R77.2@3399.95,4795 C22.2@3399.95,4855
NetC25_2: C25.2 R83.1 R85.2 U13.9 | length 209.4
  Top Layer w9.45: R83.1@2279.45,4983.47 2303.43,4983.47 2323.76,5003.8 U13.9@2339.99,5003.8
  Top Layer w10: R85.2@2139,4983.47 C25.2@2206.33,4983.47 R83.1@2279.45,4983.47
NetC31_1: C31.1 R26.2 R36.1 U3.11 | length 320.6
  Top Layer w9: R26.2@523.5,2041.85 523.5,2091.1
  Top Layer w15: U3.11@441.12,2091.1 523.5,2091.1
  Top Layer w20: 523.5,2091.1 R36.1@653.88,2091.1 C31.1@712.5,2091.1
NetC31_2: C31.2 R36.2 R46.1 | length 117.2
  Top Layer w9: R36.2@653.88,2043.85 C31.2@712.5,2043.85 R46.1@771.12,2043.85
NetC32_2: C32.2 R37.2 R47.1 | length 117.2
  Top Layer w20: R37.2@653.88,897.6 C32.2@712.5,897.6 R47.1@771.12,897.6
NetC33_1: C33.1 R39.2 R40.1 R42.2 R43.1 | length 739
  Top Layer w9: v1(686.12,2146.9) R40.1@720.87,2146.9 ; R39.2@712.73,1737.75 C33.1@766.73,1737.75 ; v1(754.27,1705.44) 766.55,1717.71 766.55,1737.57 C33.1@766.73,1737.75 ; R42.2@766.73,1880.86 R43.1@766.73,1809.31 C33.1@766.73,1737.75
  Bottom Layer w9: v1(686.12,2146.9) 754.27,2078.76 v1(754.27,1705.44)
NetC34_1: C34.1 R38.2 R41.1 R44.2 R45.1 | length 531.3
  Top Layer w9: v1(686.12,1000.65) R41.1@720.87,1000.65 ; R38.2@712.73,591.49 C34.1@766.73,591.49 R45.1@766.73,663.05 R44.2@766.73,734.61 v1(766.73,765.33)
  Bottom Layer w9: v1(686.12,1000.65) 766.73,920.05 v1(766.73,765.33)
NetC38_2: C38.2 R87.1 R97.2 U13.7 | length 265.5
  Top Layer w9.45: R97.2@2108.01,5049 2143.61,5084.61 2193.78,5084.61 2212.33,5066.06 C38.2@2239.06,5066.06 2241.02,5068.03 R87.1@2292.86,5068.03 2317.72,5043.17 U13.7@2339.99,5043.17
NetC52_2: C52.2 R62.1 U11.7 U11.8 | length 172.9
  Top Layer w10: R62.1@1118.13,3771.44 C52.2@1202.08,3771.44 U11.8@1271.39,3771.44 U11.7@1291.07,3771.44
NetC53_2: C53.2 U13.3 | length 61.2
  Top Layer w9.45: U13.3@2450.22,5023.48 C53.2@2511.46,5023.48
NetC69_1: C69.1 R103.1 R105.2 U16.9 | length 286.4
  Top Layer w10: U16.9@1573.68,4775.88 1573.68,4731.82 R103.1@1588.14,4717.37 1588.14,4678.65 1640,4626.79 C69.1@1640,4598 R105.2@1640,4517
NetC77_1: C77.1 R108.1 R111.1 U16.7 | length 264.5
  Top Layer w9.45: R108.1@1528.14,4720.37 1528.14,4751.27 1534.31,4757.45 U16.7@1534.31,4775.88
  Top Layer w10: C77.1@1412.68,4599.71 1449.71,4599.71 1465.68,4615.67 R111.1@1494.18,4615.67 ; R111.1@1494.5,4616 1494.5,4651.96 1528.14,4685.59 R108.1@1528.14,4720.37
NetC80_2: C80.2 U16.3 | length 71.9
  Top Layer w9: U16.3@1554,4886.12 C80.2@1554,4958
NetC86_2: C86.2 C505.1 L20.1 U18.4 | length 340.5
  Top Layer w9: U18.4@2264.25,3824.34 2331.16,3824.34 2369.51,3785.99 2369.51,3756.78 2389.06,3737.23 v1(2415.73,3737.23) C86.2@2452.43,3737.23 L20.1@2452.43,3674.83
  Bottom Layer w9: v1(2415.73,3737.23) C505.1@2452.43,3737.23
NetC90_1: C90.1 U18.3 Y1.2 | length 566.4
  Top Layer w9: U18.3@2264.25,3804.65 2315.45,3804.65 2345.24,3774.86 2345.24,3597.07 2396.19,3546.12 C90.1@2491.76,3546.12 Y1.2@2619.41,3546.12
NetC91_1: C91.1 U18.2 Y1.1 | length 732.9
  Top Layer w9: U18.2@2264.25,3784.97 2304.01,3784.97 2322.02,3766.96 2322.02,3564.63 2501.94,3384.7 Y1.1@2619.41,3384.7 C91.1@2619.41,3291.29
NetC93_1: C93.1 L22.1 U21.5
NetC98_1: C98.1 L500.1 U22.1 | length 162.9
  Top Layer w9: U22.1@3080.35,2647.55 3080.35,2667.71 3086.56,2673.92 3102.88,2673.92 3110.35,2681.4 C98.1@3110.35,2717.1 v1(3110.35,2752.8)
  Bottom Layer w9: L500.1@3110.35,2717.1 v1(3110.35,2752.8)
NetC99_1: C99.1 L501.1 U23.1 | length 162.9
  Top Layer w9: U23.1@3080.35,1501.29 3080.35,1521.46 3086.56,1527.67 3102.88,1527.67 3110.35,1535.14 C99.1@3110.35,1570.84 v1(3110.35,1606.54)
  Bottom Layer w9: L501.1@3110.35,1570.84 v1(3110.35,1606.54)
NetC100_1: C100.1 R158.2 U23.12 | length 122.4
  Top Layer w9: U23.12@3115.78,1465.86 3123.47,1465.86 ccw(c3123.47,1480.38) 3133.74,1470.11 cw(c3139.39,1464.46) 3139.39,1472.45 3171.63,1472.45 cw(c3171.63,1466.41) R158.2@3175.9,1470.68 C100.1@3235.9,1470.68
NetC100_2: C100.2 J20.1 | length 301.4
  Top Layer w9: C100.2@3283.15,1470.68 J20.1@3283.15,1772.06
NetC101_1: C101.1 R158.1 U23.10 | length 122.4
  Top Layer w9: U23.10@3115.78,1426.49 3123.47,1426.49 cw(c3123.47,1411.97) 3133.74,1422.24 ccw(c3139.39,1427.89) 3139.39,1419.89 3171.63,1419.89 ccw(c3171.63,1425.93) 3175.9,1421.66 C101.1@3235.9,1421.66
NetC101_2: C101.2 J21.1 | length 301.4
  Top Layer w9: J21.1@3283.15,1122.06 C101.2@3283.15,1423.44
NetC102_1: C102.1 R159.2 U22.12 | length 122.4
  Top Layer w9: U22.12@3115.78,2612.11 3123.47,2612.11 ccw(c3123.47,2626.63) 3133.74,2616.36 cw(c3139.39,2610.71) 3139.39,2618.71 3171.63,2618.71 cw(c3171.63,2612.67) R159.2@3175.9,2616.94 C102.1@3235.9,2616.94
NetC102_2: C102.2 J22.1 | length 301.4
  Top Layer w9: C102.2@3283.15,2616.94 J22.1@3283.15,2918.32
NetC103_1: C103.1 R159.1 U22.10 | length 122.4
  Top Layer w9: U22.10@3115.78,2572.74 3123.47,2572.74 cw(c3123.47,2558.22) 3133.74,2568.49 ccw(c3139.39,2574.14) 3139.39,2566.15 3171.63,2566.15 ccw(c3171.63,2572.19) 3175.9,2567.92 C103.1@3235.9,2567.92
NetC103_2: C103.2 J23.1 | length 301.4
  Top Layer w9: J23.1@3283.15,2268.31 C103.2@3283.15,2569.69
NetC106_1: C106.1 C107.1 C108.1 FB1.1 U15.10 U15.11 U15.12 U15.13 U15.14 U15.15 U15.27
  other v2: 2510.04,5464 2550.39,5464 2510.04,5489.59 2550.39,5489.59
NetC110_1: C110.1 C111.1 C112.1 FB2.1 U28.10 U28.11 U28.12 U28.13 U28.14 U28.15 U28.27
  other v2: 400,5347.5 440.35,5347.5 400,5373.09 440.35,5373.09
NetC114_2: C114.2 U26.5 | length 62.1
  Top Layer w9: U26.5@2839.99,5060.91 2853.74,5060.91 2870.83,5078 C114.2@2895,5078
NetC117_2: C117.2 C118.2 C125.2 C126.2 C127.2 C128.2 FB3.1 R178.1 U30.4 U30.7 | length 790.3
  Top Layer w7.87: R178.1@16,4920 45.76,4920 71.54,4894.22 U30.7@87.09,4894.22
  Top Layer w9.36: R178.1@16,4920 v1(16,4958.39)
  Bottom Layer w10: v1@16.66,4959.04 655.75,4959.04 v1(677.7,4937.09)
NetC120_1: C120.1 U26.10 | length 151.6
  Top Layer w8: C120.1@2647.17,5071.53 2647.18,5049.53 2657.25,5039.46 2731.19,5039.46 2749.11,5021.54 U26.10@2765.19,5021.54
NetC120_2: C120.2 U26.9 | length 75.5
  Top Layer w9: C120.2@2702.29,5071.53 2720.15,5071.53 2750.46,5041.22 U26.9@2765.19,5041.22
NetC121_1: C121.1 R86.1 R88.1 R90.2 U26.11
NetC122_2: C122.2 R92.1 R99.1 R100.1 U26.6
NetC123_1: C123.1 R101.1 R109.1 U27.8 U27.9 U27.10
NetC129_2: C129.2 R177.1 R179.2 U31.3 | length 202.3
  Top Layer w10: U31.3@1097.32,4799.58 C129.2@1097.32,4738.72 R177.1@1097.32,4664 R179.2@1164,4664
NetC132_2: C132.2 C133.2 R116.2 R117.2 U27.7 U29.7 | length 724.1
  Top Layer w9.45: U27.7@197.12,4229.31 210.01,4229.31 v1(224.9,4214.42) ; U29.7@202.12,3858.31 228.16,3858.31 v1(240.38,3846.1)
  Top Layer w15: v1(224.9,4214.42) 227.23,4214.42 238.04,4203.61 238.04,4197.31 251.03,4184.31 C132.2@253,4184.31 C133.2@319.18,4184.31 R116.2@386,4184.31 R117.2@446,4184.31
  Bottom Layer w15: v1(224.9,4214.42) 282.39,4156.93 282.39,3888.11 v1(240.38,3846.1)
NetC134_1: C134.1 R167.1 R174.1 U29.8 U29.9 U29.10
NetC141_1: C141.1 U31.14 | length 62.3
  Top Layer w10: U31.14@1071.73,4982.65 C141.1@1071.73,5045
NetC144_1: C144.1 U15.21 | length 80.1
  Top Layer w9.84: 2359.8,5477.04 2368.91,5467.94 U15.21@2388.98,5467.94
  Top Layer w10: C144.1@2317.64,5489 2347.84,5489 2359.8,5477.04
NetC147_1: C147.1 U28.21 | length 69.6
  Top Layer w9.84: 258.87,5351.43 U28.21@278.94,5351.43
  Top Layer w10: C147.1@214.5,5364 246.3,5364 258.87,5351.43
NetC527_1: C527.1 R517.2 R520.1 R521.2 U503.6 | length 328.5
  Bottom Layer w9: U503.6@760.83,156.96 849.41,156.96 C527.1@867.3,174.85 R521.2@867.3,264.7 R520.1@929.57,264.7 R517.2@992.1,264.7
NetC527_2: C527.2 R519.1 U503.7 | length 176.8
  Bottom Layer w9: U503.7@760.83,131.37 847.79,131.37 C527.2@867.3,111.86 R519.1@929.57,111.86
NetC533_1: C533.1 R522.2 R525.1 R526.2 U505.6 | length 308.5
  Bottom Layer w9: U505.6@649,1495.27 717.58,1495.27 C533.1@735.47,1513.16 R526.2@735.47,1603 R525.1@797.74,1603 R522.2@860.28,1603
NetC533_2: C533.2 R524.1 U505.7 | length 156.8
  Bottom Layer w9: U505.7@649,1469.68 715.96,1469.68 C533.2@735.47,1450.17 R524.1@797.74,1450.16
NetC553_1: C553.1 R538.1 R542.2 R549.2 U503.2 | length 314.3
  Bottom Layer w9: R549.2@284.92,164.07 347.32,164.07 R538.1@409.65,164.07 C553.1@472.06,164.07 496.57,164.07 529.26,131.37 U503.2@585.63,131.37
NetC553_2: C553.2 R529.1 U503.1 | length 192.4
  Bottom Layer w9: C553.2@472.06,101.08 476.76,105.78 U503.1@585.63,105.78 R529.1@585.63,28.9
NetC558_1: C558.1 R547.1 R550.2 R554.2 U505.2 | length 314.3
  Bottom Layer w9: R554.2@173.09,1502.37 R550.2@235.49,1502.37 R547.1@297.83,1502.37 C558.1@360.23,1502.37 392.93,1469.68 U505.2@473.81,1469.68
NetC558_2: C558.2 R534.1 U505.1 | length 192.4
  Bottom Layer w9: C558.2@360.23,1439.38 364.94,1444.09 U505.1@473.81,1444.09 R534.1@473.81,1367.21
NetC562_1: C562.1 R17.2 U3.4 | length 156.6
  Top Layer w9: R17.2@296.02,1959.96 299.79,1963.74 ccw(c256.48,2007.05) v1(317.73,2007.05) 317.73,2037.47 cw(c328.71,2037.47) 320.94,2045.23 325,2049.29 cw(c330.88,2043.41) U3.4@330.88,2051.73
  Bottom Layer w9: C562.1@286.05,1968.37 317.73,2000.05 v1(317.73,2007.05)
NetC563_1: C563.1 R18.2 U4.4 | length 180.3
  Top Layer w9: R18.2@296.02,813.71 296.02,848.02 299.64,851.64 v1(299.64,884.71) 320.18,905.25 U4.4@330.66,905.25
  Bottom Layer w9: C563.1@286.05,822.11 286.05,871.12 v1(299.64,884.71)
NetD5_2: D5.2 R110.2 | length 78.9
  Top Layer w9: R110.2@1566.06,3828.94 D5.2@1644.96,3828.94
NetD6_1: D6.1 R134.1 | length 65.7
  Top Layer w17.72: D6.1@2113.77,3492.21 R134.1@2179.49,3492.21
NetJ1_1: J1.1 R1.2 R3.2 R5.1 R7.2 | length 444.7
  Top Layer w9: R5.1@-36.62,2091 -36.62,1993.13 R3.2@13.5,1943 13.5,1906.91 12.35,1905.75 R1.2@12.35,1876.22 R7.2@67.77,1876.22
  Top Layer w20: J1.1@-190,2090.92 R5.1@-36.7,2090.92
NetJ2_1: J2.1 R2.2 R4.2 R6.1 R8.2 | length 447.4
  Top Layer w9: R6.1@-32.62,945 -32.62,841.13 R4.2@13.5,795 13.5,760.65 12.35,759.49 R2.2@12.35,729.96 R8.2@67.77,729.96
  Top Layer w20: J2.1@-190,945 R6.1@-32.62,945
NetJ3_3: J3.3 R1.1 | length 307
  Top Layer w9: J3.3@-134.53,1644.06 -134.53,1754.88 cw(c-51.05,1754.88) -110.08,1813.91 cw(c-74.11,1777.94) -74.11,1828.81 -25.27,1828.81 cw(c-25.27,1775.61) R1.1@12.35,1813.23
NetJ4_3: J4.3 R2.1 | length 307
  Top Layer w9: J4.3@-134.53,497.81 -134.53,608.63 cw(c-51.05,608.63) -110.08,667.66 cw(c-74.11,631.68) -74.11,682.56 -25.27,682.56 cw(c-25.27,629.35) R2.1@12.35,666.97
NetJ8_1: J8.1 R122.2 | length 728.4
  Top Layer w20: R122.2@1108.62,870 1160,870 cw(c1160,850) 1180,850 ccw(c1195,850) 1195,835 1550,835 cw(c1550,735) 1650,735 J8.1@1650,625
NetJ9_1: J9.1 R118.2 | length 724.1
  Top Layer w20: R118.2@1108.62,2015 1165,2015 cw(c1165,1990) 1190,1990 ccw(c1210,1990) 1210,1970 1550,1970 cw(c1550,1870) 1650,1870 J9.1@1650,1770
NetJ10_1: J10.1 R121.2 | length 724.1
  Top Layer w20: R121.2@1108.27,2184.43 1164.65,2184.43 ccw(c1164.65,2209.43) 1189.65,2209.43 cw(c1209.65,2209.43) 1209.65,2229.43 1549.65,2229.43 ccw(c1549.65,2329.43) 1649.65,2329.43 J10.1@1649.65,2429.43
NetJ11_1: J11.1 R125.2 | length 728.4
  Top Layer w20: R125.2@1108.62,1040 1160,1040 ccw(c1160,1060) 1180,1060 cw(c1195,1060) 1195,1075 1550,1075 ccw(c1550,1175) 1650,1175 J11.1@1650,1285
NetJ12_1: J12.1 T1.1 | length 799.3
  Top Layer w20: T1.1@1337.29,2158.93 1767.05,2158.93 ccw(c1767.05,2224.09) 1832.21,2224.09 cw(c1912.21,2224.09) 1912.21,2304.09 J12.1@2052.21,2304.09 ; J12.1@2049,2306 cw(c2049,2305) J12.1@2050,2305
NetJ13_1: J13.1 T1.3 | length 797.8
  Top Layer w20: T1.3@1335.08,2040.16 1764.84,2040.16 cw(c1764.84,1975) 1830,1975 ccw(c1910,1975) 1910,1895 J13.1@2050,1895
NetJ14_1: J14.1 T2.1 | length 797.8
  Top Layer w20: T2.1@1335.04,1014.84 1739.84,1014.84 ccw(c1739.84,1090) 1815,1090 cw(c1885,1090) 1885,1160 J14.1@2050,1160
NetJ15_1: J15.1 T2.3 | length 797.8
  Top Layer w20: T2.3@1335.04,895.16 1739.84,895.16 cw(c1739.84,820) 1815,820 ccw(c1885,820) 1885,750 J15.1@2050,750
NetJ16_5: J16.5 R142.2 | length 124.2
  Top Layer w9: R142.2@2918.16,4024.35 J16.5@2918.16,4148.56
NetJ18_1: J18.1 R152.1 | length 101.9
  Top Layer w9: J18.1@3041.57,3742.21 R152.1@3041.57,3844.13
NetJ18_3: J18.3 R151.2 | length 100.9
  Top Layer w9: R151.2@3041.57,3441.35 J18.3@3041.57,3542.21
NetJ19_1: J19.1 R156.1 | length 101.9
  Top Layer w9: J19.1@3171.8,3742.21 R156.1@3171.8,3844.13
NetJ19_3: J19.3 R157.2 | length 100.9
  Top Layer w9: R157.2@3171.8,3441.35 J19.3@3171.8,3542.21
NetJ24_1: J24.1 R162.1 | length 101.9
  Top Layer w9: J24.1@3302.04,3742.21 R162.1@3302.04,3844.13
NetJ24_3: J24.3 R161.2 | length 100.9
  Top Layer w9: R161.2@3302.04,3441.35 J24.3@3302.04,3542.21
NetJ25_1: J25.1 R164.1 | length 101.9
  Top Layer w9: J25.1@3432.28,3742.21 R164.1@3432.28,3844.13
NetJ25_3: J25.3 R163.2 | length 100.9
  Top Layer w9: R163.2@3432.28,3441.35 J25.3@3432.28,3542.21
NetJ26_1: J26.1 R141.1 | length 987.9
  Top Layer w10: R141.1@2737.88,3820.37 v1(2737.88,3857.69) ; v1(3425.01,4149.47) 3455.74,4180.2 J26.1@3554.92,4180.2
  Signal 2 w10: v1(2737.88,3857.69) 3133.26,3857.69 v1@3425.01,4149.44
NetJ26_2: J26.2 R138.1 | length 1190.3
  Top Layer w11: R138.1@2515.43,3862.03 2538.13,3884.74 2716.19,3884.74 2762.64,3931.18 2902.53,3931.18 3016.24,4044.89 3263.32,4044.89 3437.37,4218.94 3513.22,4218.94 3520.47,4211.69 J26.2@3554.92,4211.69
NetJ26_3: J26.3 R137.1 | length 1190.3
  Top Layer w11: R137.1@2515.43,3924.44 2538.13,3901.74 2709.15,3901.74 2755.6,3948.18 2895.49,3948.18 3009.2,4061.89 3256.28,4061.89 3430.33,4235.94 3513.22,4235.94 3520.47,4243.19 J26.3@3554.92,4243.19
NetJ27_1: J27.1 R165.1 | length 101.9
  Top Layer w9: J27.1@3562.51,3742.21 R165.1@3562.51,3844.13
NetJ27_3: J27.3 R166.2 | length 100.9
  Top Layer w9: R166.2@3562.51,3441.35 J27.3@3562.51,3542.21
NetJ28_1: J28.1 T1.2 | length 1165.6
  Top Layer w20: T1.2@1335.08,2100 2499.5,2100 2499.5,2100.5 J28.1@2500,2100
NetJ29_1: J29.1 T2.2 | length 1164.8
  Top Layer w20: T2.2@1335.04,955 J29.1@2499.79,955
NetJ31_1: J31.1 R28.1 | length 96.4
  Top Layer w8: J31.1@1951.03,3083.36 1951.03,3178.03 R28.1@1952.27,3179.28
NetJ31_3: J31.3 R63.2 | length 109.3
  Top Layer w8: R63.2@1949.77,2774.55 1951.03,2775.8 J31.3@1951.03,2883.36
NetJ32_1: J32.1 R29.1 | length 101.6
  Top Layer w8: R29.1@2299.7,2883.22 J32.1@2401.29,2883.22
NetJ32_3: J32.3 R64.2 | length 106.5
  Top Layer w8: J32.3@2601.29,2883.22 R64.2@2707.75,2883.22
NetL1_2: L1.2 R3.1 | length 60.9
  Top Layer w13.68: R3.1@74.08,1941.35 L1.2@74.08,2002.29
NetL2_2: L2.2 R4.1 | length 47.4
  Top Layer w13.68: L2.2@76.34,842.29 76.34,836.39 76.5,836.23 R4.1@76.5,795
NetL16_1: L16.1 U30.2 | length 178.1
  Top Layer w7.87: U30.2@133.35,4837.13 133.35,4660.46 L16.1@134.36,4659.45
NetR7_1: R7.1 R13.2 | length 186.5
  Top Layer w9: R7.1@67.77,1836.85 ccw(c153.79,1836.85) 92.96,1776.02 112.45,1756.54 ccw(c162.48,1806.57) 162.48,1735.81 R13.2@198.34,1735.81
NetR8_1: R8.1 R14.2 | length 186.5
  Top Layer w9: R8.1@67.77,690.59 ccw(c153.79,690.59) 92.96,629.76 112.45,610.28 ccw(c162.48,660.32) 162.48,589.55 R14.2@198.34,589.55
NetR9_1: R9.1 R12.1 | length 63.5
  Top Layer w9: R12.1@159.5,687.29 R9.1@159.5,750.77
NetR10_1: R10.1 R11.1 | length 63.5
  Top Layer w9: R11.1@159.5,1833.55 R10.1@159.5,1897.02
NetR13_1: R13.1 R551.2 U1.3 | length 109.1
  Top Layer w9: R13.1@237.71,1735.81 v1(266.68,1735.8) U1.3@317.8,1735.81
  Bottom Layer w9: R551.2@237.71,1735.81 v1(266.68,1735.8)
NetR14_1: R14.1 R552.2 U2.3 | length 109.1
  Top Layer w9: R14.1@237.71,589.55 v1(266.68,589.55) U2.3@317.81,589.55
  Bottom Layer w9: R552.2@237.71,589.55 v1(266.68,589.55)
NetR15_2: R15.2 U3.3 | length 77.8
  Top Layer w9: R15.2@261.14,2043.85 ccw(c261.14,2108.53) 306.88,2062.8 311.19,2067.11 cw(c321.58,2056.72) 321.58,2071.41 U3.3@330.88,2071.41
NetR16_2: R16.2 U4.3 | length 77.8
  Top Layer w9: R16.2@261.14,897.6 ccw(c261.14,962.27) 306.88,916.54 311.19,920.85 cw(c321.58,910.46) 321.58,925.16 U4.3@330.88,925.16
NetR19_1: R19.1 U3.6 | length 74.2
  Top Layer w9: U3.6@376.16,2026.13 376.16,1998.77 ccw(c406.83,1998.77) 385.14,1977.09 R19.1@401.22,1961
NetR20_1: R20.1 U4.6 | length 74.2
  Top Layer w9: U4.6@376.16,879.88 376.16,852.51 ccw(c406.83,852.51) 385.14,830.84 R20.1@401.22,814.75
NetR21_2: R21.2 U3.7 | length 83.4
  Top Layer w9: U3.7@395.85,2026.13 395.85,2020.41 ccw(c425.29,2020.41) 404.47,1999.59 R21.2@443.05,1961
NetR22_2: R22.2 U4.7 | length 83.4
  Top Layer w9: U4.7@395.85,879.88 395.85,874.15 ccw(c425.29,874.15) 404.47,853.33 R22.2@443.05,814.75
NetR26_1: R26.1 R30.2 | length 80.7
  Top Layer w9: R30.2@560.74,1963.85 ccw(c536.6,1987.99) 570.74,1987.99 R26.1@570.74,2041.85
NetR27_1: R27.1 R31.2 | length 80.7
  Top Layer w9: R31.2@560.74,817.59 ccw(c536.6,841.74) 570.74,841.74 R27.1@570.74,895.59
NetR32_1: R32.1 R34.2 R39.1 U1.6 | length 189
  Top Layer w9: U1.6@532.36,1735.81 611.53,1735.8 R34.2@613.48,1737.75 ; R32.1@613.48,1682.66 R34.2@613.48,1737.75 ; R39.1@665.48,1737.75 R34.2@613.48,1737.75
NetR33_1: R33.1 R35.2 R38.1 U2.6 | length 189
  Top Layer w9: U2.6@532.37,589.55 570.75,589.55 572.7,591.49 R35.2@613.48,591.49 ; R33.1@613.48,536.41 R35.2@613.48,591.49 ; R38.1@665.48,591.49 R35.2@613.48,591.49
NetR34_1: R34.1 R530.2 U1.7 | length 129
  Top Layer w9: U1.7@532.36,1785.81 v1(579.9,1785.8) 612.66,1785.81 R34.1@613.48,1784.99
  Bottom Layer w9: R530.2@532.37,1785.8 v1(579.9,1785.8)
NetR35_1: R35.1 R531.2 U2.7 | length 129
  Top Layer w9: U2.7@532.36,639.55 579.91,639.55 612.66,639.55 R35.1@613.48,638.74
  Bottom Layer w9: R531.2@532.37,639.55 v1(579.9,639.55)
NetR40_2: R40.2 U7.6 | length 78.9
  Top Layer w9: R40.2@768.12,2146.9 cw(c768.12,2121.9) 785.8,2139.58 811.61,2113.77 ccw(c818.82,2120.98) 818.82,2110.78 U7.6@833.57,2110.78
NetR41_2: R41.2 U8.6 | length 78.9
  Top Layer w9: R41.2@768.12,1000.65 cw(c768.12,975.65) 785.8,993.33 811.61,967.51 ccw(c818.82,974.73) 818.82,964.53 U8.6@833.57,964.53
NetR46_2: R46.2 U7.7 | length 62.5
  Top Layer w15: R46.2@771.12,2091.1 U7.7@833.57,2091.1
NetR47_2: R47.2 U8.7 | length 62.5
  Top Layer w9: R47.2@771.12,944.84 U8.7@833.57,944.84
NetR53_1: R53.1 U7.2 | length 82
  Top Layer w9: R53.1@903.22,2253.77 903.22,2239.68 ccw(c930.28,2239.68) 911.14,2220.55 cw(c894.07,2203.47) 918.22,2203.47 U7.2@918.22,2175.74
NetR54_1: R54.1 U8.2 | length 82
  Top Layer w9: R54.1@903.22,1107.52 903.22,1093.43 ccw(c930.28,1093.43) 911.15,1074.3 cw(c894.07,1057.22) 918.22,1057.22 U8.2@918.22,1029.49
NetR58_1: R58.1 U7.1 | length 82
  Top Layer w9: U7.1@937.9,2175.74 937.9,2189.95 cw(c974.92,2189.95) 948.75,2216.13 ccw(c938.71,2226.16) 952.9,2226.16 R58.1@952.9,2253.77
NetR59_1: R59.1 U8.1 | length 82
  Top Layer w9: U8.1@937.9,1029.49 937.9,1043.7 cw(c974.92,1043.7) 948.75,1069.87 ccw(c938.71,1079.91) 952.9,1079.91 R59.1@952.9,1107.52
NetR65_1: R65.1 R130.2 U32.5 | length 1587.6
  Top Layer w8: v1(1483.9,3416.35) U32.5@1483.9,3445.94
  Top Layer w10: R65.1@1483.9,3386.76 v1(1483.9,3416.35) ; R65.1@1487.25,3385.14 R65.1@1496.44,3375.96 ; R130.2@2015.2,4351.77 v1(2015.2,4395.58)
  Bottom Layer w10: v1(1483.9,3416.35) 1546.78,3479.23 1546.78,3883.86 1629.55,3966.63 1629.55,4179.88 1743.34,4293.67 1743.34,4446.48 1772.98,4476.12 1962.95,4476.12 2015.2,4423.87 v1(2015.2,4395.58)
